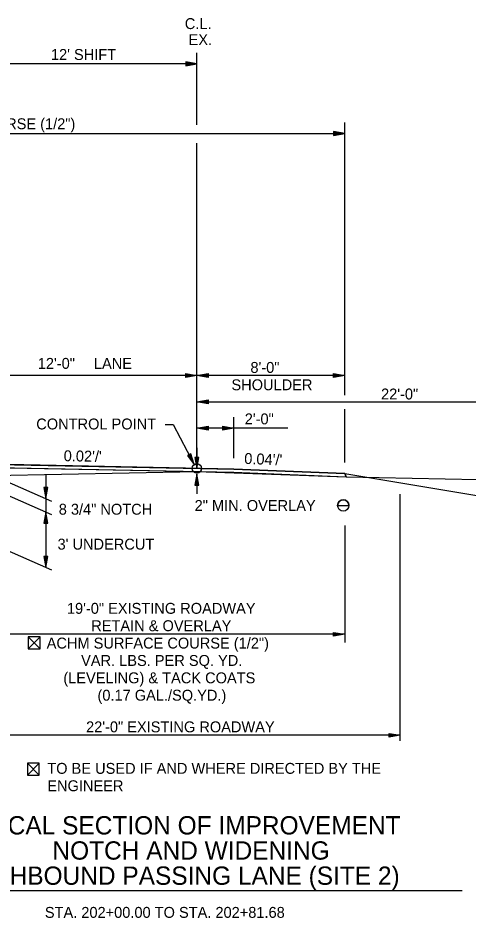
# Model space of a CAD drawing. Extents: x 1398565 to 1398920, y 1968324 to 1968581.
# Drawn here: x 1398643.9 to 1398668.26, y 1968374.84 to 1968423.53 of the extents above; entities that cross this region are included whole.
import ezdxf

# ---------------------------------------------------------------- set-up
doc = ezdxf.new("R2010")
doc.units = 0
for name, color, linetype in [('10', 7, 'Continuous'), ('19', 7, 'Continuous'), ('42', 7, 'Continuous'), ('7', 7, 'Continuous'), ('Level 9', 7, 'Continuous')]:
    doc.layers.add(name, color=color, linetype=linetype)

msp = doc.modelspace()

# ---------------------------------------------------------------- linework, layer by layer
at = {"layer": '10'}
for p, q in [((1398661.199, 1968397.157), (1398661.81, 1968397.157)), ((1398644.455, 1968390.043), (1398645.096, 1968389.401)), ((1398645.096, 1968390.043), (1398644.455, 1968389.401)), ((1398644.836, 1968389.401), (1398644.847, 1968389.401)), ((1398644.416, 1968383.214), (1398645.057, 1968382.573)), ((1398645.057, 1968383.214), (1398644.416, 1968382.573)), ((1398644.798, 1968382.573), (1398644.809, 1968382.573))]:
    msp.add_line(p, q, dxfattribs=at)
for points in [[(1398644.847, 1968389.401), (1398645.096, 1968389.401), (1398645.096, 1968390.043), (1398644.455, 1968390.043), (1398644.455, 1968389.401), (1398644.836, 1968389.401)], [(1398644.809, 1968382.573), (1398645.057, 1968382.573), (1398645.057, 1968383.214), (1398644.416, 1968383.214), (1398644.416, 1968382.573), (1398644.798, 1968382.573)]]:
    msp.add_lwpolyline(points, dxfattribs=at)
msp.add_circle((1398661.505, 1968397.157), 0.306, dxfattribs=at)
msp.add_arc((1398661.505, 1968397.157), 0.306, 0, 180, dxfattribs=at)
at = {"layer": '19'}
for p, q in [((1398653.586, 1968421.049), (1398641.586, 1968421.049)), ((1398652.986, 1968421.154), (1398652.986, 1968420.944)), ((1398653.586, 1968421.049), (1398652.986, 1968421.154)), ((1398653.426, 1968421.064), (1398652.986, 1968421.099)), ((1398652.986, 1968420.944), (1398653.586, 1968421.049)), ((1398652.986, 1968420.994), (1398653.426, 1968421.034)), ((1398661.586, 1968403.121), (1398661.586, 1968417.879)), ((1398621.586, 1968417.279), (1398661.586, 1968417.279)), ((1398660.986, 1968417.385), (1398660.986, 1968417.175)), ((1398661.586, 1968417.279), (1398660.986, 1968417.385)), ((1398661.426, 1968417.294), (1398660.986, 1968417.33)), ((1398660.986, 1968417.175), (1398661.586, 1968417.279)), ((1398660.986, 1968417.225), (1398661.426, 1968417.264)), ((1398661.586, 1968404.184), (1398641.586, 1968404.184)), ((1398652.986, 1968404.079), (1398652.986, 1968404.289)), ((1398652.986, 1968404.289), (1398653.586, 1968404.184)), ((1398652.986, 1968404.234), (1398653.426, 1968404.199)), ((1398653.586, 1968404.184), (1398652.986, 1968404.079)), ((1398653.426, 1968404.169), (1398652.986, 1968404.129)), ((1398653.586, 1968404.184), (1398654.186, 1968404.289)), ((1398654.186, 1968404.079), (1398653.586, 1968404.184)), ((1398653.746, 1968404.199), (1398654.186, 1968404.234)), ((1398654.186, 1968404.129), (1398653.746, 1968404.169)), ((1398654.186, 1968404.289), (1398654.186, 1968404.079)), ((1398660.986, 1968404.079), (1398660.986, 1968404.289)), ((1398660.986, 1968404.289), (1398661.586, 1968404.184)), ((1398660.986, 1968404.234), (1398661.426, 1968404.199)), ((1398661.586, 1968404.184), (1398660.986, 1968404.079)), ((1398661.426, 1968404.169), (1398660.986, 1968404.129)), ((1398653.586, 1968402.763), (1398654.186, 1968402.868)), ((1398653.586, 1968402.763), (1398675.586, 1968402.763)), ((1398654.186, 1968402.658), (1398653.586, 1968402.763)), ((1398653.746, 1968402.778), (1398654.186, 1968402.813)), ((1398654.186, 1968402.708), (1398653.746, 1968402.748)), ((1398654.186, 1968402.868), (1398654.186, 1968402.658)), ((1398661.586, 1968399.489), (1398661.586, 1968402.368)), ((1398655.586, 1968399.72), (1398655.586, 1968401.942)), ((1398653.586, 1968401.342), (1398654.186, 1968401.447)), ((1398658.512, 1968401.342), (1398653.586, 1968401.342)), ((1398654.186, 1968401.237), (1398653.586, 1968401.342)), ((1398653.746, 1968401.357), (1398654.186, 1968401.392)), ((1398654.186, 1968401.287), (1398653.746, 1968401.327)), ((1398654.186, 1968401.447), (1398654.186, 1968401.237)), ((1398654.986, 1968401.237), (1398654.986, 1968401.447)), ((1398654.986, 1968401.447), (1398655.586, 1968401.342)), ((1398654.986, 1968401.392), (1398655.426, 1968401.357)), ((1398655.586, 1968401.342), (1398654.986, 1968401.237)), ((1398655.426, 1968401.327), (1398654.986, 1968401.287)), ((1398653.586, 1968400.269), (1398653.586, 1968399.16)), ((1398653.263, 1968399.946), (1398653.077, 1968399.851)), ((1398653.077, 1968399.851), (1398653.44, 1968399.364)), ((1398653.119, 1968399.869), (1398653.354, 1968399.5)), ((1398653.378, 1968399.51), (1398653.217, 1968399.917)), ((1398653.44, 1968399.364), (1398653.263, 1968399.946)), ((1398653.691, 1968399.76), (1398653.481, 1968399.76)), ((1398653.481, 1968399.76), (1398653.586, 1968399.16)), ((1398653.536, 1968399.76), (1398653.571, 1968399.32)), ((1398653.586, 1968399.16), (1398653.691, 1968399.76)), ((1398653.601, 1968399.32), (1398653.641, 1968399.76)), ((1398641.586, 1968399.4), (1398655.586, 1968399.12)), ((1398641.586, 1968399.234), (1398655.586, 1968398.954)), ((1398655.586, 1968399.12), (1398661.586, 1968398.88)), ((1398642.967, 1968398.606), (1398645.71, 1968397.396)), ((1398645.408, 1968398.808), (1398645.408, 1968397.532)), ((1398653.586, 1968398.848), (1398653.481, 1968398.248)), ((1398653.571, 1968398.688), (1398653.536, 1968398.248)), ((1398653.586, 1968398.874), (1398653.586, 1968397.791)), ((1398653.691, 1968398.248), (1398653.586, 1968398.848)), ((1398653.641, 1968398.248), (1398653.601, 1968398.688)), ((1398655.586, 1968398.954), (1398661.671, 1968398.71)), ((1398661.586, 1968398.88), (1398675.586, 1968396.547)), ((1398661.586, 1968398.88), (1398661.671, 1968398.71)), ((1398645.513, 1968398.132), (1398645.303, 1968398.132)), ((1398645.303, 1968398.132), (1398645.408, 1968397.532)), ((1398645.358, 1968398.132), (1398645.393, 1968397.692)), ((1398645.408, 1968397.532), (1398645.513, 1968398.132)), ((1398645.423, 1968397.692), (1398645.463, 1968398.132)), ((1398653.481, 1968398.248), (1398653.691, 1968398.248)), ((1398642.967, 1968397.877), (1398645.71, 1968396.667)), ((1398664.586, 1968384.418), (1398664.586, 1968397.772)), ((1398645.408, 1968397.532), (1398645.408, 1968393.8)), ((1398645.408, 1968396.8), (1398645.303, 1968396.2)), ((1398645.393, 1968396.64), (1398645.358, 1968396.2)), ((1398645.513, 1968396.2), (1398645.408, 1968396.8)), ((1398645.463, 1968396.2), (1398645.423, 1968396.64)), ((1398645.303, 1968396.2), (1398645.513, 1968396.2)), ((1398661.586, 1968396.08), (1398661.586, 1968389.741)), ((1398642.967, 1968394.877), (1398645.71, 1968393.667)), ((1398645.513, 1968394.4), (1398645.303, 1968394.4)), ((1398645.303, 1968394.4), (1398645.408, 1968393.8)), ((1398645.358, 1968394.4), (1398645.393, 1968393.96)), ((1398645.408, 1968393.8), (1398645.513, 1968394.4)), ((1398645.423, 1968393.96), (1398645.463, 1968394.4)), ((1398660.986, 1968390.084), (1398660.986, 1968390.294)), ((1398660.986, 1968390.294), (1398661.586, 1968390.189)), ((1398661.586, 1968390.189), (1398642.586, 1968390.189)), ((1398660.986, 1968390.239), (1398661.426, 1968390.204)), ((1398661.586, 1968390.189), (1398660.986, 1968390.084)), ((1398661.426, 1968390.174), (1398660.986, 1968390.134)), ((1398664.586, 1968384.725), (1398642.586, 1968384.725)), ((1398663.986, 1968384.62), (1398663.986, 1968384.83)), ((1398663.986, 1968384.83), (1398664.586, 1968384.725)), ((1398663.986, 1968384.775), (1398664.426, 1968384.74)), ((1398664.586, 1968384.725), (1398663.986, 1968384.62)), ((1398664.426, 1968384.71), (1398663.986, 1968384.67)), ((1398638.967, 1968376.334), (1398667.947, 1968376.334))]:
    msp.add_line(p, q, dxfattribs=at)
msp.add_lwpolyline([(1398651.861, 1968401.541), (1398652.307, 1968401.541), (1398653.44, 1968399.364)], dxfattribs=at)
msp.add_lwpolyline([(1398621.506, 1968398.71), (1398627.586, 1968398.954), (1398641.586, 1968399.234), (1398655.586, 1968398.954), (1398661.671, 1968398.71), (1398661.586, 1968398.88), (1398655.586, 1968399.12), (1398641.586, 1968399.4), (1398627.586, 1968399.12), (1398621.591, 1968398.881)], close=True, dxfattribs=at)
at = {"layer": '42'}
for points in [[(1398642.586, 1968398.774), (1398653.586, 1968398.994)], [(1398653.586, 1968398.994), (1398661.671, 1968398.71), (1398670.586, 1968398.534), (1398679.441, 1968396.073), (1398684.522, 1968396.615), (1398701.339, 1968396.526)]]:
    msp.add_lwpolyline(points, dxfattribs=at)
at = {"layer": '7'}
for p, q in [((1398653.586, 1968417.751), (1398653.586, 1968421.649)), ((1398653.586, 1968399.4), (1398653.586, 1968416.757))]:
    msp.add_line(p, q, dxfattribs=at)
at = {"layer": 'Level 9'}
msp.add_circle((1398653.586, 1968399.16), 0.25, dxfattribs=at)

# ---------------------------------------------------------------- texts
at = {"layer": '10'}
for s, height, p in [('12\'-0" ', 0.59, (1398644.974, 1968404.547)), ('LANE', 0.59, (1398648.012, 1968404.547)), ('8\'-0" ', 0.59, (1398656.482, 1968404.329)), ('SHOULDER', 0.59, (1398655.455, 1968403.389)), ('22\'-0"', 0.59, (1398663.551, 1968402.891)), ('2\'-0"', 0.59, (1398656.174, 1968401.545)), ('CONTROL POINT', 0.59001, (1398644.891, 1968401.269)), ('8 3/4" NOTCH', 0.59001, (1398646.109, 1968396.658)), ('2" MIN. OVERLAY', 0.59001, (1398653.462, 1968396.86)), ("3' UNDERCUT", 0.59001, (1398646.043, 1968394.769)), ('19\'-0" EXISTING ROADWAY', 0.59001, (1398646.551, 1968391.297)), ('RETAIN & OVERLAY', 0.59001, (1398647.866, 1968390.357)), ('ACHM SURFACE COURSE (1/2")', 0.59001, (1398645.455, 1968389.417)), ('VAR. LBS. PER SQ. YD.', 0.59001, (1398647.318, 1968388.477)), ('(LEVELING) & TACK COATS', 0.59001, (1398646.356, 1968387.537)), ('(0.17 GAL./SQ.YD.)', 0.59001, (1398648.205, 1968386.597)), ('22\'-0" EXISTING ROADWAY', 0.59001, (1398647.586, 1968384.886)), ('TO BE USED IF AND WHERE DIRECTED BY THE ', 0.59001, (1398645.489, 1968382.64)), ('ENGINEER', 0.59, (1398645.489, 1968381.7)), ('STA. 202+00.00 TO STA. 202+81.68', 0.59001, (1398645.357, 1968374.85))]:
    msp.add_text(s, height=height, rotation=360, dxfattribs=at).set_placement(p)
at = {"layer": '19'}
msp.add_text('C.L.', height=0.59, dxfattribs=at).set_placement((1398652.931, 1968422.927))
for s, height, rotation, p in [('EX.', 0.59, 360, (1398653.136, 1968422.059)), ("12' SHIFT", 0.59, 360, (1398645.686, 1968421.256)), ("0.02'/'", 0.59, 358.8542, (1398646.372, 1968399.554)), ("0.04'/'", 0.59, 357.7094, (1398656.138, 1968399.41)), ('TYPICAL SECTION OF IMPROVEMENT', 0.98999, 360, (1398640.404, 1968379.36)), ('NOTCH AND WIDENING', 0.98999, 360, (1398645.767, 1968377.999)), ('SOUTHBOUND PASSING LANE (SITE 2)', 0.98999, 360, (1398639.769, 1968376.637))]:
    msp.add_text(s, height=height, rotation=rotation, dxfattribs=at).set_placement(p)
at = {"layer": '42'}
msp.add_text('40\'-0" ACHM SURFACE COURSE (1/2")', height=0.59001, rotation=360, dxfattribs=at).set_placement((1398632.748, 1968417.51))

doc.saveas('drawing.dxf')
